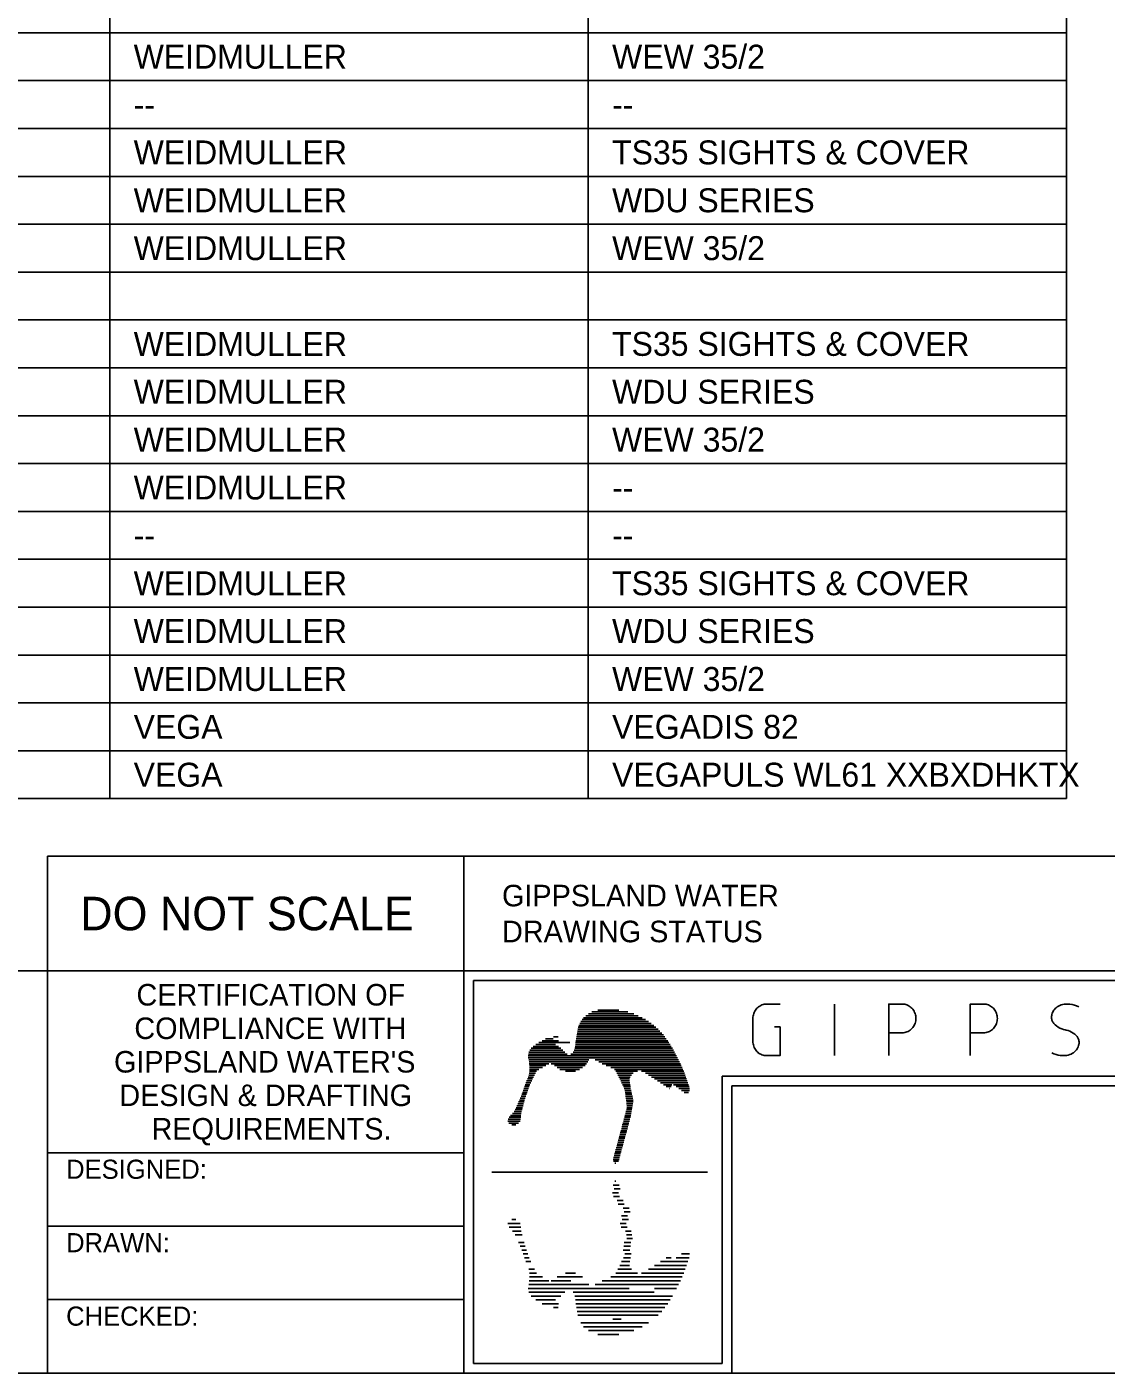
# Model space of a CAD drawing. Extents: x 841 to 1682, y 0 to 594.
# Drawn here: x 1431.3 to 1544.1, y 15 to 155.6 of the extents above; entities that cross this region are included whole.
import ezdxf

# ---------------------------------------------------------------- set-up
doc = ezdxf.new("R2010")
doc.units = 0
for name, color, linetype in [('A1BORDER', 7, 'Continuous'), ('BASE', 7, 'Continuous'), ('Default', 7, 'Continuous'), ('Level 1', 7, 'Continuous')]:
    doc.layers.add(name, color=color, linetype=linetype)

msp = doc.modelspace()

# ---------------------------------------------------------------- linework, layer by layer
at = {"layer": 'A1BORDER'}
for p, q in [((1433.5, 69), (1433.5, 15)), ((1433.5, 69), (1670, 69)), ((1477, 69), (1477, 15)), ((869, 57), (1670, 57)), ((1478, 56), (1629, 56)), ((1478, 56), (1478, 16)), ((1489.53, 52.12), (1495.64, 52.12)), ((1489.74, 52.32), (1495.24, 52.32)), ((1490.02, 52.52), (1494.76, 52.52)), ((1490.39, 52.72), (1494.15, 52.72)), ((1491.01, 52.92), (1493.2, 52.92)), ((1488.88, 50.72), (1497.5, 50.72)), ((1488.91, 50.92), (1497.3, 50.92)), ((1488.96, 51.12), (1497.08, 51.12)), ((1489.03, 51.32), (1496.85, 51.32)), ((1489.12, 51.52), (1496.59, 51.52)), ((1489.23, 51.72), (1496.31, 51.72)), ((1489.37, 51.92), (1496, 51.92)), ((1484.54, 49.32), (1486.57, 49.32)), ((1484.85, 49.52), (1488.09, 49.52)), ((1485.18, 49.72), (1486.89, 49.72)), ((1485.54, 49.92), (1486.36, 49.92)), ((1486.37, 50.12), (1486.86, 50.12)), ((1488.66, 49.32), (1498.57, 49.32)), ((1488.69, 49.52), (1498.44, 49.52)), ((1488.71, 49.72), (1498.31, 49.72)), ((1488.75, 49.92), (1498.17, 49.92)), ((1488.78, 50.12), (1498.02, 50.12)), ((1488.81, 50.32), (1497.86, 50.32)), ((1488.85, 50.52), (1497.69, 50.52)), ((1483.73, 48.12), (1499.25, 48.12)), ((1483.74, 47.92), (1499.35, 47.92)), ((1483.75, 48.32), (1487.79, 48.32)), ((1483.81, 48.52), (1487.55, 48.52)), ((1483.9, 48.72), (1487.37, 48.72)), ((1484.04, 48.92), (1487.16, 48.92)), ((1484.26, 49.12), (1486.9, 49.12)), ((1488.19, 48.32), (1499.14, 48.32)), ((1488.42, 48.52), (1499.03, 48.52)), ((1488.54, 48.72), (1498.92, 48.72)), ((1488.61, 48.92), (1498.8, 48.92)), ((1488.63, 49.12), (1498.68, 49.12)), ((1483.79, 47.72), (1490.08, 47.72)), ((1483.83, 47.52), (1489.95, 47.52)), ((1483.85, 47.31), (1485.88, 47.31)), ((1483.87, 47.12), (1485.57, 47.12)), ((1483.87, 46.52), (1484.6, 46.52)), ((1483.88, 46.92), (1485.23, 46.92)), ((1483.88, 46.72), (1484.83, 46.72)), ((1486.14, 47.31), (1489.83, 47.31)), ((1486.49, 47.12), (1489.67, 47.12)), ((1486.76, 46.92), (1489.42, 46.92)), ((1487.05, 46.72), (1489.11, 46.72)), ((1487.62, 46.52), (1488.67, 46.52)), ((1490.72, 47.72), (1499.45, 47.72)), ((1491.12, 47.52), (1499.55, 47.52)), ((1491.48, 47.31), (1499.64, 47.31)), ((1491.87, 47.12), (1499.73, 47.12)), ((1492.36, 46.92), (1499.82, 46.92)), ((1492.76, 46.72), (1499.9, 46.72)), ((1492.88, 46.52), (1495.15, 46.52)), ((1495.57, 46.52), (1499.99, 46.52)), ((1483.43, 45.12), (1483.9, 45.12)), ((1483.5, 45.32), (1484, 45.32)), ((1483.57, 45.52), (1484.1, 45.52)), ((1483.65, 45.72), (1484.2, 45.72)), ((1483.72, 45.92), (1484.3, 45.92)), ((1483.79, 46.12), (1484.4, 46.12)), ((1483.84, 46.32), (1484.5, 46.32)), ((1492.99, 46.32), (1494.71, 46.32)), ((1493.1, 46.12), (1494.52, 46.12)), ((1493.2, 45.92), (1494.4, 45.92)), ((1493.31, 45.72), (1494.33, 45.72)), ((1493.41, 45.52), (1494.31, 45.52)), ((1493.5, 45.32), (1494.34, 45.32)), ((1493.6, 45.12), (1494.38, 45.12)), ((1496, 46.32), (1500.07, 46.32)), ((1496.31, 46.12), (1500.14, 46.12)), ((1496.62, 45.92), (1500.22, 45.92)), ((1496.93, 45.72), (1500.29, 45.72)), ((1497.24, 45.52), (1500.35, 45.52)), ((1497.55, 45.32), (1500.42, 45.32)), ((1497.86, 45.12), (1498.74, 45.12)), ((1498.91, 45.12), (1500.48, 45.12)), ((1504, 46), (1629, 46)), ((1504, 16), (1504, 46)), ((1505, 45), (1670, 45)), ((1505, 15), (1505, 45)), ((1482.91, 43.72), (1483.41, 43.72)), ((1482.99, 43.92), (1483.48, 43.92)), ((1483.06, 44.12), (1483.55, 44.12)), ((1483.13, 44.32), (1483.62, 44.32)), ((1483.21, 44.52), (1483.69, 44.52)), ((1483.28, 44.72), (1483.76, 44.72)), ((1483.35, 44.92), (1483.83, 44.92)), ((1493.69, 44.92), (1494.41, 44.92)), ((1493.78, 44.72), (1494.44, 44.72)), ((1493.83, 44.52), (1494.48, 44.52)), ((1493.86, 44.32), (1494.53, 44.32)), ((1493.89, 44.12), (1494.57, 44.12)), ((1493.91, 43.92), (1494.62, 43.92)), ((1493.94, 43.72), (1494.67, 43.72)), ((1498.17, 44.92), (1498.68, 44.92)), ((1498.51, 44.72), (1498.54, 44.72)), ((1499.19, 44.92), (1500.54, 44.92)), ((1499.47, 44.72), (1500.59, 44.72)), ((1499.75, 44.52), (1500.58, 44.52)), ((1500.02, 44.32), (1500.47, 44.32)), ((1482.25, 42.31), (1483.04, 42.31)), ((1482.37, 42.52), (1483.09, 42.52)), ((1482.46, 42.72), (1483.15, 42.72)), ((1482.55, 42.92), (1483.2, 42.92)), ((1482.64, 43.12), (1483.25, 43.12)), ((1482.73, 43.32), (1483.3, 43.32)), ((1482.82, 43.51), (1483.35, 43.51)), ((1493.95, 42.31), (1494.53, 42.31)), ((1493.97, 43.51), (1494.71, 43.51)), ((1493.99, 42.52), (1494.57, 42.52)), ((1494, 43.32), (1494.69, 43.32)), ((1494.02, 43.12), (1494.67, 43.12)), ((1494.03, 42.72), (1494.61, 42.72)), ((1494.05, 42.92), (1494.64, 42.92)), ((1481.62, 41.32), (1482.88, 41.32)), ((1481.63, 41.52), (1482.93, 41.52)), ((1481.72, 41.12), (1482.73, 41.12)), ((1481.73, 41.72), (1482.95, 41.72)), ((1481.9, 41.92), (1482.97, 41.92)), ((1482.03, 40.92), (1482.43, 40.92)), ((1482.1, 42.12), (1483, 42.12)), ((1493.57, 40.92), (1494.2, 40.92)), ((1493.63, 41.12), (1494.26, 41.12)), ((1493.68, 41.32), (1494.31, 41.32)), ((1493.74, 41.52), (1494.37, 41.52)), ((1493.79, 41.72), (1494.41, 41.72)), ((1493.85, 41.92), (1494.45, 41.92)), ((1493.9, 42.12), (1494.49, 42.12)), ((1493.2, 39.52), (1493.82, 39.52)), ((1493.25, 39.72), (1493.88, 39.72)), ((1493.3, 39.92), (1493.93, 39.92)), ((1493.36, 40.12), (1493.99, 40.12)), ((1493.41, 40.32), (1494.04, 40.32)), ((1493.47, 40.52), (1494.1, 40.52)), ((1493.52, 40.72), (1494.15, 40.72)), ((1477, 38), (1433.5, 38)), ((1492.82, 38.12), (1493.44, 38.12)), ((1492.87, 38.32), (1493.5, 38.32)), ((1492.92, 38.52), (1493.55, 38.52)), ((1492.98, 38.72), (1493.61, 38.72)), ((1493.03, 38.92), (1493.66, 38.92)), ((1493.09, 39.12), (1493.72, 39.12)), ((1493.14, 39.32), (1493.77, 39.32)), ((1492.63, 37.32), (1493.23, 37.32)), ((1492.64, 37.12), (1493.17, 37.12)), ((1492.65, 37.52), (1493.28, 37.52)), ((1492.71, 37.72), (1493.34, 37.72)), ((1492.76, 37.92), (1493.39, 37.92)), ((1492.79, 36.92), (1492.9, 36.92)), ((1479.93, 35.98), (1502.47, 35.98)), ((1492.54, 33.84), (1493.17, 33.84)), ((1492.63, 34.64), (1493.23, 34.64)), ((1492.71, 34.24), (1493.34, 34.24)), ((1492.79, 35.04), (1492.9, 35.04)), ((1492.65, 33.44), (1493.28, 33.44)), ((1493.03, 33.04), (1493.66, 33.04)), ((1493.14, 32.64), (1493.77, 32.64)), ((1482.03, 31.04), (1482.43, 31.04)), ((1493.47, 31.44), (1494.1, 31.44)), ((1493.57, 31.04), (1494.2, 31.04)), ((1493.66, 32.24), (1494.29, 32.24)), ((1493.77, 31.84), (1494.4, 31.84)), ((1477, 30.34), (1433.5, 30.34)), ((1481.62, 30.64), (1482.88, 30.64)), ((1481.73, 30.24), (1482.95, 30.24)), ((1482.1, 29.84), (1483, 29.84)), ((1493.34, 30.64), (1493.97, 30.64)), ((1493.45, 30.24), (1494.07, 30.24)), ((1493.9, 29.84), (1494.49, 29.84)), ((1482.37, 29.44), (1483.09, 29.44)), ((1482.73, 28.64), (1483.3, 28.64)), ((1482.91, 28.24), (1483.41, 28.24)), ((1493.72, 28.24), (1494.44, 28.24)), ((1493.77, 28.64), (1494.46, 28.64)), ((1493.99, 29.44), (1494.57, 29.44)), ((1494.05, 29.04), (1494.64, 29.04)), ((1483.06, 27.84), (1483.55, 27.84)), ((1483.21, 27.44), (1483.69, 27.44)), ((1483.35, 27.04), (1483.83, 27.04)), ((1493.66, 27.84), (1494.35, 27.84)), ((1493.69, 27.04), (1494.41, 27.04)), ((1493.83, 27.44), (1494.48, 27.44)), ((1498.17, 27.04), (1498.68, 27.04)), ((1499.19, 27.04), (1500.54, 27.04)), ((1499.75, 27.44), (1500.58, 27.44)), ((1483.5, 26.64), (1484, 26.64)), ((1483.79, 25.84), (1484.4, 25.84)), ((1483.87, 25.44), (1484.6, 25.44)), ((1487.62, 25.44), (1488.67, 25.44)), ((1492.88, 25.44), (1495.15, 25.44)), ((1493.1, 25.84), (1494.52, 25.84)), ((1493.31, 26.24), (1494.33, 26.24)), ((1493.5, 26.64), (1494.34, 26.64)), ((1495.57, 25.44), (1499.99, 25.44)), ((1496.31, 25.84), (1500.14, 25.84)), ((1496.93, 26.24), (1500.29, 26.24)), ((1497.55, 26.64), (1500.42, 26.64)), ((1483.79, 24.24), (1490.08, 24.24)), ((1483.85, 24.65), (1485.88, 24.65)), ((1483.88, 25.04), (1485.23, 25.04)), ((1486.14, 24.65), (1488.18, 24.65)), ((1486.76, 25.04), (1489.42, 25.04)), ((1490.72, 24.24), (1499.45, 24.24)), ((1491.48, 24.65), (1499.64, 24.65)), ((1492.36, 25.04), (1499.82, 25.04)), ((1477, 22.67), (1433.5, 22.67)), ((1483.73, 23.84), (1494.27, 23.84)), ((1483.81, 23.44), (1487.55, 23.44)), ((1484.04, 23.04), (1487.16, 23.04)), ((1484.54, 22.64), (1486.57, 22.64)), ((1488.42, 23.44), (1496.89, 23.44)), ((1488.61, 23.04), (1498.8, 23.04)), ((1488.66, 22.64), (1498.57, 22.64)), ((1496.94, 23.84), (1499.25, 23.84)), ((1485.18, 22.24), (1486.89, 22.24)), ((1486.37, 21.84), (1486.86, 21.84)), ((1488.71, 22.24), (1498.31, 22.24)), ((1488.78, 21.84), (1498.02, 21.84)), ((1488.85, 21.44), (1497.69, 21.44)), ((1488.91, 21.04), (1497.3, 21.04)), ((1489.23, 20.24), (1496.31, 20.24)), ((1489.53, 19.84), (1495.64, 19.84)), ((1492.57, 20.64), (1493.44, 20.64)), ((1490.02, 19.44), (1494.76, 19.44)), ((1491.01, 19.04), (1493.2, 19.04)), ((1504, 16), (1478, 16)), ((1670, 15), (869, 15))]:
    msp.add_line(p, q, dxfattribs=at)
for points in [[(1509.49, 51.15), (1510.06, 51.15), (1510.06, 48.16), (1508.64, 48.16), (1508.51, 48.16), (1508.39, 48.18), (1508.28, 48.21), (1508.15, 48.25), (1508.04, 48.3), (1507.93, 48.36), (1507.82, 48.43), (1507.73, 48.51), (1507.64, 48.6), (1507.55, 48.7), (1507.48, 48.8), (1507.41, 48.91), (1507.35, 49.02), (1507.31, 49.14), (1507.27, 49.27), (1507.24, 49.39), (1507.22, 49.52), (1507.22, 49.66), (1507.22, 52.05), (1507.22, 52.18), (1507.24, 52.31), (1507.27, 52.43), (1507.31, 52.56), (1507.35, 52.67), (1507.41, 52.79), (1507.48, 52.9), (1507.55, 53), (1507.64, 53.1), (1507.73, 53.19), (1507.82, 53.27), (1507.93, 53.34), (1508.04, 53.4), (1508.15, 53.45), (1508.28, 53.49), (1508.39, 53.52), (1508.51, 53.54), (1508.64, 53.54), (1510.06, 53.54)], [(1515.74, 48.16), (1515.74, 53.54)], [(1521.42, 48.16), (1521.42, 53.54), (1522.84, 53.54), (1522.96, 53.54), (1523.08, 53.52), (1523.2, 53.49), (1523.32, 53.45), (1523.43, 53.4), (1523.54, 53.34), (1523.65, 53.27), (1523.74, 53.19), (1523.84, 53.1), (1523.92, 53), (1523.99, 52.9), (1524.06, 52.79), (1524.12, 52.67), (1524.17, 52.56), (1524.21, 52.43), (1524.23, 52.31), (1524.25, 52.18), (1524.26, 52.05), (1524.25, 51.91), (1524.23, 51.78), (1524.21, 51.66), (1524.17, 51.53), (1524.12, 51.42), (1524.06, 51.3), (1523.99, 51.19), (1523.92, 51.09), (1523.84, 50.99), (1523.74, 50.9), (1523.65, 50.82), (1523.54, 50.75), (1523.43, 50.69), (1523.32, 50.64), (1523.2, 50.6), (1523.08, 50.57), (1522.96, 50.55), (1522.84, 50.55), (1521.42, 50.55)], [(1529.93, 48.16), (1529.93, 53.54), (1531.35, 53.54), (1531.47, 53.54), (1531.59, 53.52), (1531.71, 53.49), (1531.83, 53.45), (1531.94, 53.4), (1532.05, 53.34), (1532.16, 53.27), (1532.26, 53.19), (1532.35, 53.1), (1532.43, 53), (1532.51, 52.9), (1532.57, 52.79), (1532.63, 52.67), (1532.68, 52.56), (1532.72, 52.43), (1532.75, 52.31), (1532.76, 52.18), (1532.77, 52.05), (1532.76, 51.91), (1532.75, 51.78), (1532.72, 51.66), (1532.68, 51.53), (1532.63, 51.42), (1532.57, 51.3), (1532.51, 51.19), (1532.43, 51.09), (1532.35, 50.99), (1532.26, 50.9), (1532.16, 50.82), (1532.05, 50.75), (1531.94, 50.69), (1531.83, 50.64), (1531.71, 50.6), (1531.59, 50.57), (1531.47, 50.55), (1531.35, 50.55), (1529.93, 50.55)], [(1538.45, 48.46), (1538.67, 48.36), (1538.9, 48.27), (1539.12, 48.21), (1539.36, 48.17), (1539.6, 48.16), (1539.84, 48.16), (1539.87, 48.16), (1540.03, 48.18), (1540.18, 48.21), (1540.33, 48.26), (1540.48, 48.32), (1540.62, 48.4), (1540.72, 48.46), (1540.81, 48.53), (1540.9, 48.61), (1540.98, 48.69), (1541.05, 48.78), (1541.11, 48.88), (1541.17, 48.99), (1541.22, 49.09), (1541.25, 49.21), (1541.28, 49.32), (1541.29, 49.36), (1541.3, 49.44), (1541.3, 49.52), (1541.3, 49.61), (1541.29, 49.69), (1541.27, 49.77), (1541.25, 49.86), (1541.22, 49.93), (1541.18, 50.01), (1541.14, 50.09), (1541.09, 50.15), (1541.04, 50.21), (1541.01, 50.25), (1540.85, 50.39), (1540.69, 50.51), (1540.52, 50.61), (1540.34, 50.7), (1540.15, 50.78), (1539.95, 50.83), (1539.87, 50.85), (1539.68, 50.9), (1539.49, 50.96), (1539.3, 51.04), (1539.12, 51.14), (1538.96, 51.26), (1538.8, 51.39), (1538.73, 51.45), (1538.67, 51.51), (1538.62, 51.57), (1538.58, 51.64), (1538.53, 51.71), (1538.5, 51.79), (1538.47, 51.87), (1538.46, 51.95), (1538.44, 52.04), (1538.43, 52.12), (1538.43, 52.21), (1538.44, 52.29), (1538.45, 52.35), (1538.47, 52.46), (1538.51, 52.58), (1538.55, 52.69), (1538.61, 52.79), (1538.67, 52.89), (1538.74, 52.99), (1538.82, 53.07), (1538.9, 53.15), (1538.99, 53.23), (1539.02, 53.24), (1539.15, 53.33), (1539.3, 53.4), (1539.44, 53.45), (1539.6, 53.5), (1539.75, 53.52), (1539.87, 53.54), (1540.11, 53.55), (1540.35, 53.53), (1540.58, 53.49), (1540.82, 53.43), (1541.04, 53.35), (1541.27, 53.25)]]:
    msp.add_lwpolyline(points, dxfattribs=at)
at = {"layer": 'Default'}
msp.add_line((1350, 80), (1540, 80), dxfattribs=at)
at = {"layer": 'Level 1'}
for p, q in [((1540, 75), (1540, 568.5)), ((1440, 558.75), (1440, 75)), ((1490, 558.75), (1490, 75)), ((1350, 155), (1540, 155)), ((1340, 150), (1540, 150)), ((1350, 145), (1540, 145)), ((1350, 140), (1540, 140)), ((1350, 135), (1540, 135)), ((1340, 130), (1540, 130)), ((1350, 125), (1540, 125)), ((1350, 120), (1540, 120)), ((1350, 115), (1540, 115)), ((1350, 110), (1540, 110)), ((1340, 105), (1540, 105)), ((1350, 100), (1540, 100)), ((1350, 95), (1540, 95)), ((1350, 90), (1540, 90)), ((1340, 85), (1540, 85)), ((1340, 75), (1540, 75))]:
    msp.add_line(p, q, dxfattribs=at)

# ---------------------------------------------------------------- texts
at = {"layer": 'A1BORDER'}
for s, height, p in [('DO NOT SCALE', 3.5, (1436.922, 61.25)), ('GIPPSLAND WATER', 2.25, (1481, 63.75)), ('DRAWING STATUS', 2.25, (1481, 60)), ('CERTIFICATION OF', 2.25, (1442.795, 53.39)), ('COMPLIANCE WITH', 2.25, (1442.57, 49.89)), ("GIPPSLAND WATER'S", 2.25, (1440.446, 46.39)), ('DESIGN & DRAFTING', 2.25, (1441.004, 42.89)), ('REQUIREMENTS.', 2.25, (1444.371, 39.39)), ('DESIGNED:', 2, (1435.44, 35.29)), ('DRAWN:', 2, (1435.44, 27.62)), ('CHECKED:', 2, (1435.44, 19.95))]:
    msp.add_text(s, height=height, dxfattribs=at).set_placement(p)
at = {"layer": 'BASE'}
for s, p in [('VEGA', (1442.5, 81.25)), ('VEGADIS 82', (1492.5, 81.25)), ('VEGA', (1442.5, 76.25)), ('VEGAPULS WL61 XXBXDHKTX', (1492.5, 76.25))]:
    msp.add_text(s, height=2.5, dxfattribs=at).set_placement(p)
at = {"layer": 'Level 1'}
for s, p in [('WEIDMULLER', (1442.5, 151.25)), ('WEW 35/2', (1492.5, 151.25)), ('--', (1442.5, 146.25)), ('--', (1492.5, 146.25)), ('WEIDMULLER', (1442.5, 141.25)), ('TS35 SIGHTS & COVER', (1492.5, 141.25)), ('WEIDMULLER', (1442.5, 136.25)), ('WDU SERIES', (1492.5, 136.25)), ('WEIDMULLER', (1442.5, 131.25)), ('WEW 35/2', (1492.5, 131.25)), ('WEIDMULLER', (1442.5, 121.25)), ('TS35 SIGHTS & COVER', (1492.5, 121.25)), ('WEIDMULLER', (1442.5, 116.25)), ('WDU SERIES', (1492.5, 116.25)), ('WEIDMULLER', (1442.5, 111.25)), ('WEW 35/2', (1492.5, 111.25)), ('WEIDMULLER', (1442.5, 106.25)), ('--', (1492.5, 106.25)), ('--', (1442.5, 101.25)), ('--', (1492.5, 101.25)), ('WEIDMULLER', (1442.5, 96.25)), ('TS35 SIGHTS & COVER', (1492.5, 96.25)), ('WEIDMULLER', (1442.5, 91.25)), ('WDU SERIES', (1492.5, 91.25)), ('WEIDMULLER', (1442.5, 86.25)), ('WEW 35/2', (1492.5, 86.25))]:
    msp.add_text(s, height=2.5, dxfattribs=at).set_placement(p)

doc.saveas('drawing.dxf')
